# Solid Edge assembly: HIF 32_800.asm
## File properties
Title: Zylinder
Author: ahadarics
Template: iso assembly.asm
Last saved by: ahadarics
Revision: 59
Application: Solid Edge
Username: ahadarics
Dokumentum tartalom típus: 1
Document Number: HIF 32/800
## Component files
Prfilrohr 32_800.par
Mutter.par
Kolbenstange 32_800.par
Kit_1.par
Kit_2.par
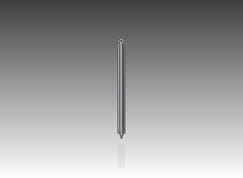
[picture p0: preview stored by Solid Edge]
